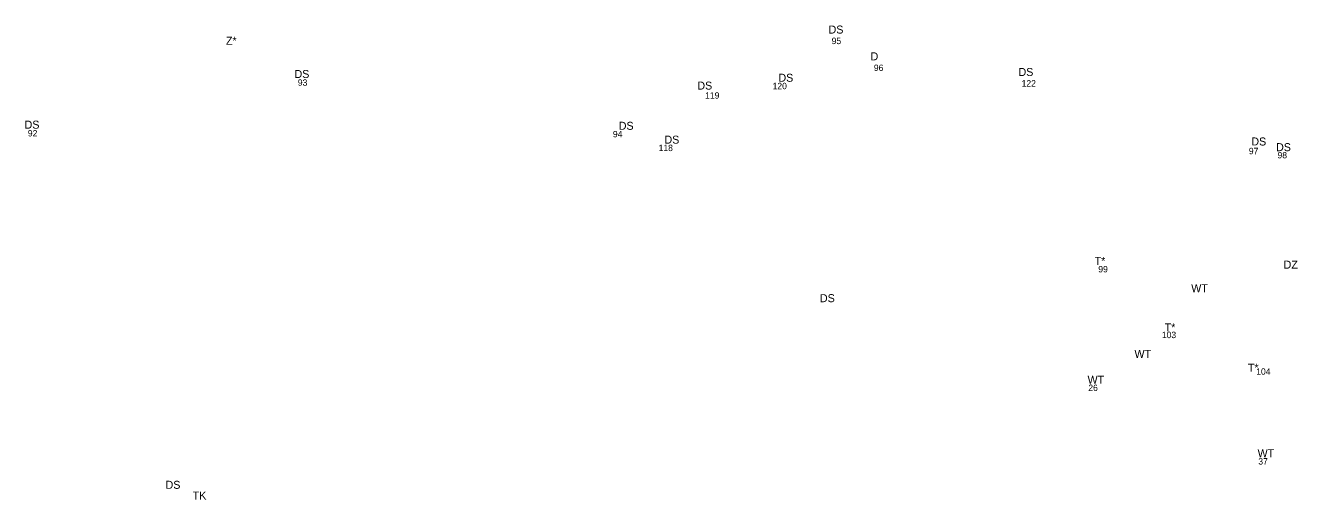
# Model space of a CAD drawing. Extents: x -521559 to -516922, y -1189648 to -1185402.
# Drawn here: x -519120 to -517530, y -1188127 to -1187535 of the extents above; entities that cross this region are included whole.
import ezdxf

# ---------------------------------------------------------------- set-up
doc = ezdxf.new("R2010")
doc.units = 0
for name, color, linetype in [('fpl_id', 7, 'Continuous'), ('s_zelen_s', 7, 'Continuous'), ('v_infrastr_n', 7, 'Continuous'), ('v_infrastr_s', 7, 'Continuous'), ('voda_n', 7, 'Continuous'), ('voda_s', 7, 'Continuous')]:
    doc.layers.add(name, color=color, linetype=linetype)

msp = doc.modelspace()

# ---------------------------------------------------------------- texts
at = {"layer": 'fpl_id'}
for s, p in [('95', (-518112.5, -1187558.6)), ('96', (-518059.8, -1187592.2)), ('93', (-518779.4, -1187610.6)), ('120', (-518186.3, -1187614.9)), ('122', (-517875.2, -1187611.6)), ('119', (-518270.6, -1187626.7)), ('92', (-519116.7, -1187673.9)), ('94', (-518385.8, -1187675)), ('118', (-518328.7, -1187692.2)), ('97', (-517591.3, -1187696.1)), ('98', (-517555.5, -1187701.3)), ('99', (-517779.4, -1187843.7)), ('103', (-517700, -1187925.8)), ('104', (-517582.1, -1187971.5)), ('26', (-517791.9, -1187991.8)), ('37', (-517579.5, -1188083.7))]:
    msp.add_text(s, height=8, dxfattribs=at).set_placement(p)
at = {"layer": 's_zelen_s'}
msp.add_text('Z*', height=10, dxfattribs=at).set_placement((-518869.2, -1187559.4))
at = {"layer": 'v_infrastr_n'}
for s, p in [('DS', (-518116.4, -1187545.4)), ('D', (-518063.9, -1187578.9)), ('DS', (-518783.6, -1187600.9)), ('DS', (-517879.1, -1187598.4)), ('DS', (-518280.3, -1187615.4)), ('DS', (-518179, -1187605.6)), ('DS', (-519120.8, -1187664.2)), ('DS', (-518378.5, -1187665.6)), ('DS', (-518321.4, -1187682.9)), ('DS', (-517588.2, -1187685.2)), ('DS', (-517557.3, -1187692.3)), ('T*', (-517784, -1187834.3)), ('T*', (-517696.5, -1187917.3)), ('T*', (-517592.5, -1187967.7))]:
    msp.add_text(s, height=10, dxfattribs=at).set_placement(p)
at = {"layer": 'v_infrastr_s'}
for s, p in [('DZ', (-517547.9, -1187839)), ('DS', (-518127.2, -1187880.9)), ('DS', (-518944.7, -1188114)), ('TK', (-518910.8, -1188127.4))]:
    msp.add_text(s, height=10, dxfattribs=at).set_placement(p)
at = {"layer": 'voda_n'}
for p in [(-517792.8, -1187982.8), (-517580.4, -1188074.6)]:
    msp.add_text('WT', height=10, dxfattribs=at).set_placement(p)
at = {"layer": 'voda_s'}
for p in [(-517663.3, -1187868.5), (-517734.2, -1187950.5)]:
    msp.add_text('WT', height=10, dxfattribs=at).set_placement(p)

doc.saveas('drawing.dxf')
